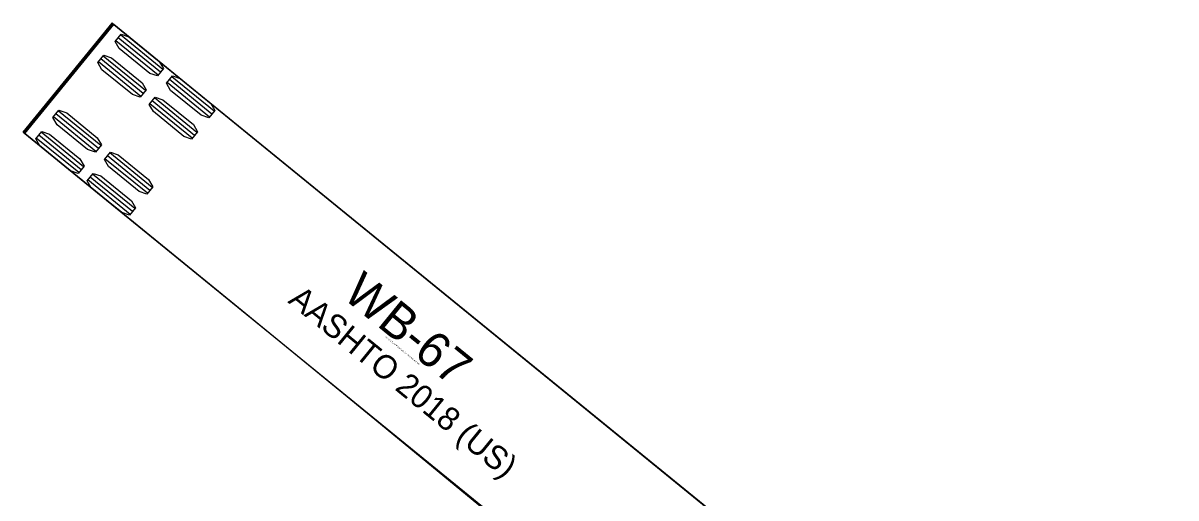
# Model space of a CAD drawing. Extents: x 973688 to 979179, y 703586 to 707602.
# Drawn here: x 973779.8 to 973849.4, y 707573 to 707601.7 of the extents above; entities that cross this region are included whole.
import ezdxf

# ---------------------------------------------------------------- set-up
doc = ezdxf.new("R2010")
doc.units = 0
doc.layers.add('0-NPLT', color=7, linetype='Continuous')

msp = doc.modelspace()

# ---------------------------------------------------------------- linework, layer by layer
at = {"layer": '0-NPLT'}
for p, q in [((973779.933, 707595.028), (973785.302, 707601.618)), ((973779.933, 707595.028), (973785.302, 707601.618)), ((973787.976, 707598.553), (973785.418, 707600.637)), ((973787.976, 707598.553), (973785.418, 707600.637)), ((973788.121, 707598.731), (973785.562, 707600.815)), ((973788.121, 707598.731), (973785.562, 707600.815)), ((973788.265, 707598.908), (973785.707, 707600.993)), ((973788.265, 707598.908), (973785.707, 707600.993)), ((973786.934, 707597.274), (973784.375, 707599.358)), ((973786.934, 707597.274), (973784.375, 707599.358)), ((973787.078, 707597.451), (973784.52, 707599.536)), ((973787.078, 707597.451), (973784.52, 707599.536)), ((973787.223, 707597.629), (973784.665, 707599.713)), ((973787.223, 707597.629), (973784.665, 707599.713)), ((973782.731, 707598.574), (973782.899, 707598.78)), ((973782.731, 707598.574), (973782.899, 707598.78)), ((973782.228, 707597.956), (973782.395, 707598.162)), ((973782.228, 707597.956), (973782.395, 707598.162)), ((973782.563, 707598.368), (973782.618, 707598.323)), ((973782.563, 707598.368), (973782.618, 707598.323)), ((973791.077, 707596.026), (973788.519, 707598.111)), ((973791.077, 707596.026), (973788.519, 707598.111)), ((973791.222, 707596.204), (973788.663, 707598.288)), ((973791.222, 707596.204), (973788.663, 707598.288)), ((973791.366, 707596.382), (973788.808, 707598.466)), ((973791.366, 707596.382), (973788.808, 707598.466)), ((973790.324, 707595.102), (973787.766, 707597.187)), ((973790.324, 707595.102), (973787.766, 707597.187)), ((973784.518, 707594.308), (973781.959, 707596.393)), ((973784.518, 707594.308), (973781.959, 707596.393)), ((973790.035, 707594.747), (973787.476, 707596.832)), ((973790.035, 707594.747), (973787.476, 707596.832)), ((973790.179, 707594.925), (973787.621, 707597.009)), ((973790.179, 707594.925), (973787.621, 707597.009)), ((973784.228, 707593.953), (973781.67, 707596.037)), ((973784.228, 707593.953), (973781.67, 707596.037)), ((973784.373, 707594.131), (973781.815, 707596.215)), ((973784.373, 707594.131), (973781.815, 707596.215)), ((973783.475, 707593.029), (973780.917, 707595.114)), ((973783.475, 707593.029), (973780.917, 707595.114)), ((973783.186, 707592.674), (973780.628, 707594.758)), ((973783.186, 707592.674), (973780.628, 707594.758)), ((973783.331, 707592.852), (973780.772, 707594.936)), ((973783.331, 707592.852), (973780.772, 707594.936)), ((973787.474, 707591.604), (973784.916, 707593.689)), ((973787.474, 707591.604), (973784.916, 707593.689)), ((973787.619, 707591.782), (973785.06, 707593.866)), ((973787.619, 707591.782), (973785.06, 707593.866)), ((973787.329, 707591.426), (973784.771, 707593.511)), ((973787.329, 707591.426), (973784.771, 707593.511)), ((973786.287, 707590.147), (973783.729, 707592.232)), ((973786.287, 707590.147), (973783.729, 707592.232)), ((973786.432, 707590.325), (973783.873, 707592.409)), ((973786.432, 707590.325), (973783.873, 707592.409)), ((973786.576, 707590.503), (973784.018, 707592.587)), ((973786.576, 707590.503), (973784.018, 707592.587))]:
    msp.add_line(p, q, dxfattribs=at)
for points in [[(973849.487, 707536.74), (973841.492, 707543.732), (973833.448, 707550.669), (973825.356, 707557.555), (973817.22, 707564.395), (973809.045, 707571.194), (973800.836, 707577.96), (973792.6, 707584.702), (973779.828, 707595.114), (973785.197, 707601.704), (973785.197, 707601.704)], [(973849.487, 707536.74), (973841.492, 707543.732), (973833.448, 707550.669), (973825.356, 707557.555), (973817.22, 707564.395), (973809.045, 707571.194), (973800.836, 707577.96), (973792.6, 707584.702), (973779.828, 707595.114), (973785.197, 707601.704), (973785.197, 707601.704)], [(973779.893, 707595.09), (973779.879, 707595.074), (973779.934, 707595.029), (973784.327, 707591.449), (973820.912, 707561.64), (973823.597, 707564.935), (973826.281, 707568.23), (973789.696, 707598.038), (973785.302, 707601.617), (973785.247, 707601.662), (973785.233, 707601.645)], [(973779.893, 707595.09), (973779.879, 707595.074), (973779.934, 707595.029), (973784.327, 707591.449), (973820.912, 707561.64), (973823.597, 707564.935), (973826.281, 707568.23), (973789.696, 707598.038), (973785.302, 707601.617), (973785.247, 707601.662), (973785.233, 707601.645)], [(973785.218, 707601.627), (973785.218, 707601.626), (973782.921, 707598.807), (973782.898, 707598.78), (973782.844, 707598.824), (973782.843, 707598.823), (973782.675, 707598.616)], [(973785.218, 707601.627), (973785.218, 707601.626), (973782.921, 707598.807), (973782.898, 707598.78), (973782.844, 707598.824), (973782.843, 707598.823), (973782.675, 707598.616)], [(973785.197, 707601.704), (973829.522, 707565.582), (973833.643, 707562.186), (973837.75, 707558.77), (973841.842, 707555.336), (973845.918, 707551.884), (973849.98, 707548.412)], [(973785.197, 707601.704), (973829.522, 707565.582), (973833.643, 707562.186), (973837.75, 707558.77), (973841.842, 707555.336), (973845.918, 707551.884), (973849.98, 707548.412)], [(973782.727, 707598.568), (973782.397, 707598.165)], [(973782.727, 707598.568), (973782.397, 707598.165)], [(973782.342, 707598.208), (973782.174, 707598.002), (973782.173, 707598), (973782.227, 707597.956), (973782.205, 707597.928), (973779.909, 707595.11), (973779.908, 707595.109)], [(973782.342, 707598.208), (973782.174, 707598.002), (973782.173, 707598), (973782.227, 707597.956), (973782.205, 707597.928), (973779.909, 707595.11), (973779.908, 707595.109)]]:
    msp.add_lwpolyline(points, dxfattribs=at)
for points in [[(973788.301, 707598.952), (973787.94, 707598.509), (973787.473, 707598.667), (973785.631, 707600.168), (973785.382, 707600.593), (973785.743, 707601.037), (973786.21, 707600.878), (973788.052, 707599.378)], [(973788.301, 707598.952), (973787.94, 707598.509), (973787.473, 707598.667), (973785.631, 707600.168), (973785.382, 707600.593), (973785.743, 707601.037), (973786.21, 707600.878), (973788.052, 707599.378)], [(973787.259, 707597.673), (973786.898, 707597.23), (973786.431, 707597.388), (973784.589, 707598.889), (973784.339, 707599.314), (973784.701, 707599.758), (973785.168, 707599.599), (973787.01, 707598.098)], [(973787.259, 707597.673), (973786.898, 707597.23), (973786.431, 707597.388), (973784.589, 707598.889), (973784.339, 707599.314), (973784.701, 707599.758), (973785.168, 707599.599), (973787.01, 707598.098)], [(973791.402, 707596.426), (973791.041, 707595.982), (973790.574, 707596.14), (973788.732, 707597.641), (973788.483, 707598.067), (973788.844, 707598.51), (973789.311, 707598.352), (973791.153, 707596.851)], [(973791.402, 707596.426), (973791.041, 707595.982), (973790.574, 707596.14), (973788.732, 707597.641), (973788.483, 707598.067), (973788.844, 707598.51), (973789.311, 707598.352), (973791.153, 707596.851)], [(973790.36, 707595.146), (973789.999, 707594.703), (973789.532, 707594.861), (973787.69, 707596.362), (973787.44, 707596.787), (973787.802, 707597.231), (973788.269, 707597.073), (973790.111, 707595.572)], [(973790.36, 707595.146), (973789.999, 707594.703), (973789.532, 707594.861), (973787.69, 707596.362), (973787.44, 707596.787), (973787.802, 707597.231), (973788.269, 707597.073), (973790.111, 707595.572)], [(973784.554, 707594.352), (973784.192, 707593.909), (973783.725, 707594.067), (973781.883, 707595.568), (973781.634, 707595.993), (973781.995, 707596.437), (973782.462, 707596.279), (973784.304, 707594.778)], [(973784.554, 707594.352), (973784.192, 707593.909), (973783.725, 707594.067), (973781.883, 707595.568), (973781.634, 707595.993), (973781.995, 707596.437), (973782.462, 707596.279), (973784.304, 707594.778)], [(973783.511, 707593.073), (973783.15, 707592.63), (973782.683, 707592.788), (973780.841, 707594.289), (973780.592, 707594.714), (973780.953, 707595.158), (973781.42, 707594.999), (973783.262, 707593.499)], [(973783.511, 707593.073), (973783.15, 707592.63), (973782.683, 707592.788), (973780.841, 707594.289), (973780.592, 707594.714), (973780.953, 707595.158), (973781.42, 707594.999), (973783.262, 707593.499)], [(973787.655, 707591.826), (973787.293, 707591.382), (973786.826, 707591.541), (973784.984, 707593.041), (973784.735, 707593.467), (973785.096, 707593.91), (973785.563, 707593.752), (973787.405, 707592.251)], [(973787.655, 707591.826), (973787.293, 707591.382), (973786.826, 707591.541), (973784.984, 707593.041), (973784.735, 707593.467), (973785.096, 707593.91), (973785.563, 707593.752), (973787.405, 707592.251)], [(973786.612, 707590.547), (973786.251, 707590.103), (973785.784, 707590.261), (973783.942, 707591.762), (973783.693, 707592.188), (973784.054, 707592.631), (973784.521, 707592.473), (973786.363, 707590.972)], [(973786.612, 707590.547), (973786.251, 707590.103), (973785.784, 707590.261), (973783.942, 707591.762), (973783.693, 707592.188), (973784.054, 707592.631), (973784.521, 707592.473), (973786.363, 707590.972)]]:
    msp.add_lwpolyline(points, close=True, dxfattribs=at)
for centre in [(973785.199, 707601.658), (973785.199, 707601.658), (973779.874, 707595.121), (973779.874, 707595.121)]:
    msp.add_circle(centre, 0.0266, dxfattribs=at)
for centre, radius, start, end in [((973785.199, 707601.658), 0.0363, 339.90536, 301.06671), ((973785.199, 707601.658), 0.0363, 339.90536, 301.06671), ((973782.702, 707598.594), 0.0352, 140.85318, 319.85359), ((973782.702, 707598.594), 0.0352, 140.85318, 319.85359), ((973782.702, 707598.594), 0.0353, 324.16409, 142.51375), ((973782.702, 707598.594), 0.0353, 324.16409, 142.51375), ((973782.369, 707598.186), 0.0354, 145.11945, 317.30491), ((973782.369, 707598.186), 0.0354, 145.11945, 317.30491), ((973782.37, 707598.186), 0.0352, 321.80224, 140.80265), ((973782.37, 707598.186), 0.0352, 321.80224, 140.80265), ((973778.325, 707596.367), 2.022, 320.82791, 321.51167), ((973778.325, 707596.367), 2.022, 320.82791, 321.51167)]:
    msp.add_arc(centre, radius, start, end, dxfattribs=at)

# ---------------------------------------------------------------- texts
for s, height, p in [('WB-67', 2.125, (973799.041, 707585.161)), ('WB-67', 2.125, (973799.041, 707585.161)), ('AASHTO 2018 (US)', 1.41667, (973795.763, 707584.862)), ('AASHTO 2018 (US)', 1.41667, (973795.763, 707584.862)), ('(c) 2021 Transoft Solutions, Inc. All rights reserved.', 0.085, (973801.683, 707582.735)), ('(c) 2021 Transoft Solutions, Inc. All rights reserved.', 0.085, (973801.683, 707582.735))]:
    msp.add_text(s, height=height, rotation=320.82791, dxfattribs=at).set_placement(p)

doc.saveas('drawing.dxf')
